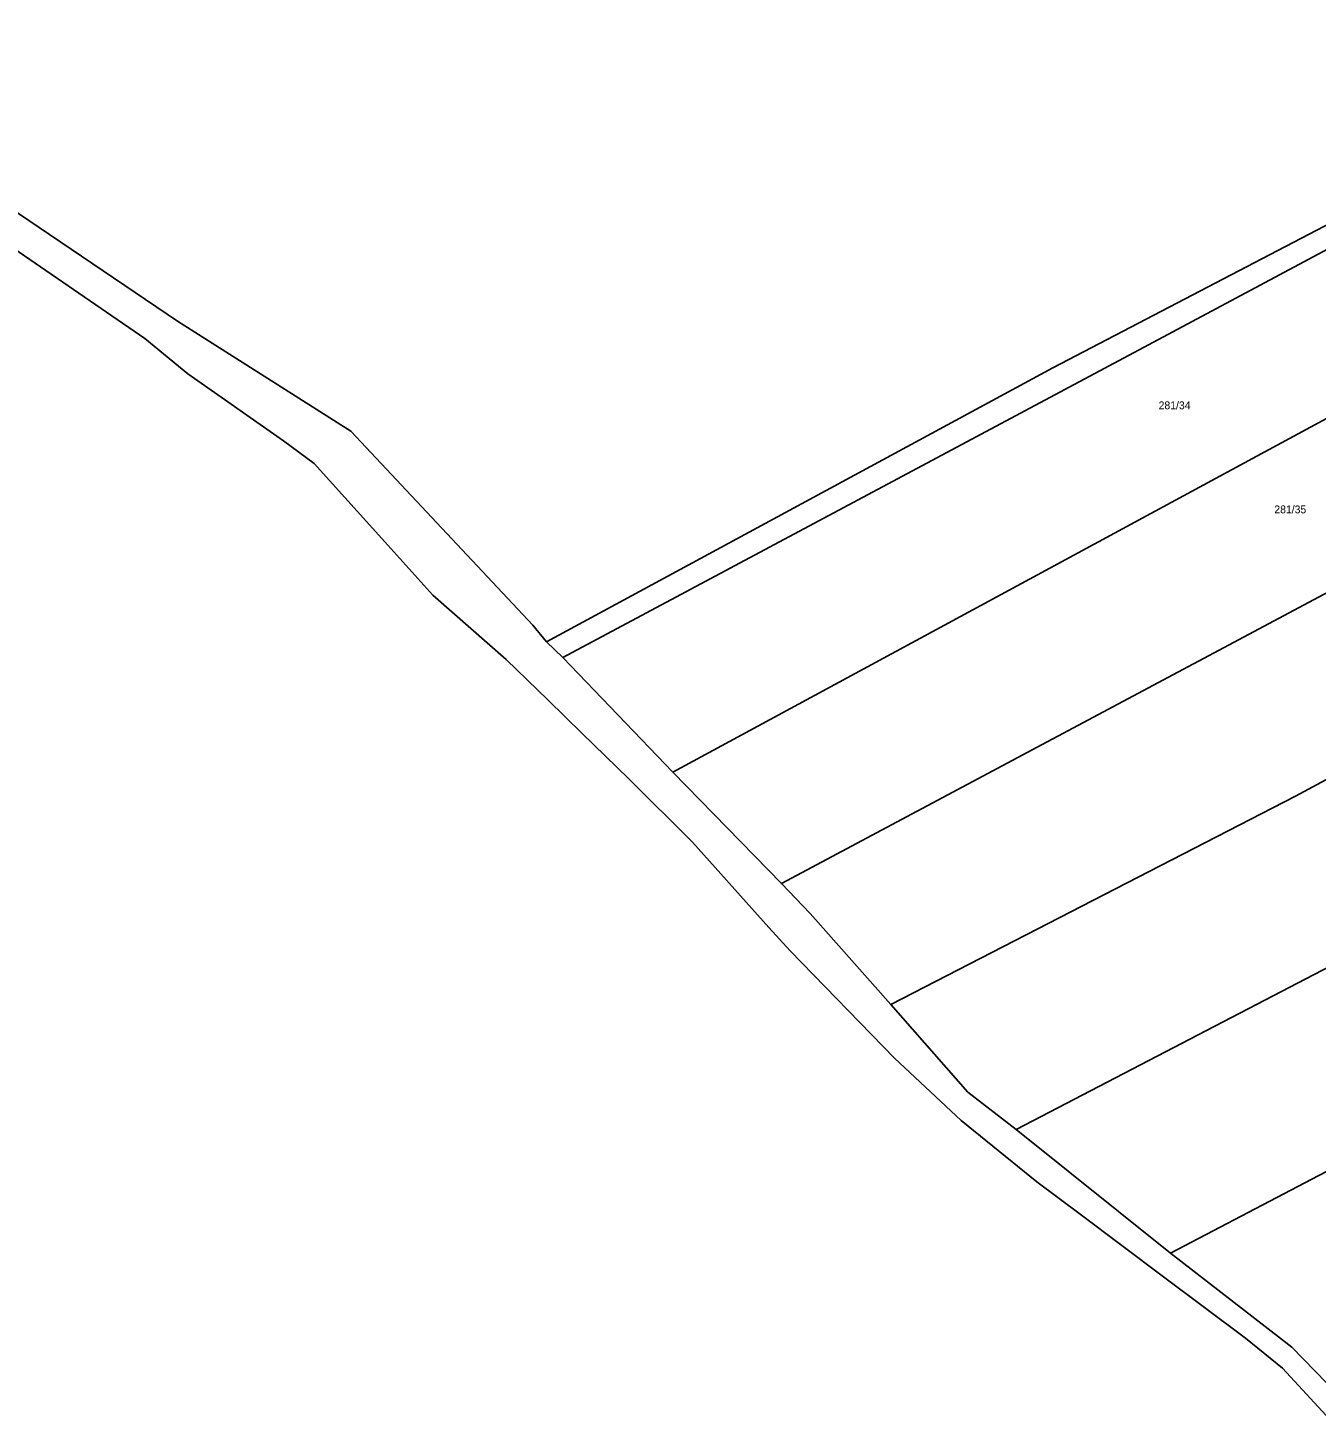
# Model space of a CAD drawing. Extents: x -779723 to -777378, y -1011169 to -1009297.
# Drawn here: x -778656.8 to -778375.8, y -1011055 to -1010750.5 of the extents above; entities that cross this region are included whole.
import ezdxf

# ---------------------------------------------------------------- set-up
doc = ezdxf.new("R2010")
doc.units = 0
doc.layers.add('KN_HRANICE', color=7, linetype='Continuous')
doc.layers.add('KN_PARCELY', color=7, linetype='Continuous')

msp = doc.modelspace()

# ---------------------------------------------------------------- linework, layer by layer
at = {"layer": 'KN_HRANICE'}
for p, q in [((-778412.34, -1010819.61), (-778282.98, -1010750.53)), ((-778676.79, -1010778.85), (-778624.16, -1010814.46)), ((-778267.44, -1010778.23), (-778392.34, -1010845.85)), ((-778631.26, -1010818.25), (-778679.13, -1010785.37)), ((-778433.26, -1010824.65), (-778357.59, -1010785.18)), ((-778624.16, -1010814.46), (-778586.31, -1010838.48)), ((-778621.86, -1010825.98), (-778631.26, -1010818.25)), ((-778540.08, -1010887.83), (-778412.34, -1010819.61)), ((-778601.01, -1010840.56), (-778621.86, -1010825.98)), ((-778543.66, -1010884.4), (-778433.26, -1010824.65)), ((-778586.31, -1010838.48), (-778546.61, -1010880.74)), ((-778594.3, -1010845.53), (-778601.01, -1010840.56)), ((-778235.35, -1010839.63), (-778380.28, -1010918.01)), ((-778578.28, -1010863.29), (-778594.3, -1010845.53)), ((-778392.34, -1010845.85), (-778516.11, -1010912.84)), ((-778568.44, -1010874.2), (-778578.28, -1010863.29)), ((-778556.56, -1010884.61), (-778568.44, -1010874.2)), ((-778492.42, -1010937.08), (-778372.93, -1010873.38)), ((-778546.61, -1010880.74), (-778543.66, -1010884.4)), ((-778543.66, -1010884.4), (-778540.08, -1010887.83)), ((-778552.44, -1010888.22), (-778556.56, -1010884.61)), ((-778543.31, -1010897.11), (-778552.44, -1010888.22)), ((-778540.08, -1010887.83), (-778516.11, -1010912.84)), ((-778535.87, -1010904.34), (-778543.31, -1010897.11)), ((-778525.77, -1010914.17), (-778535.87, -1010904.34)), ((-778511.84, -1010928.07), (-778525.77, -1010914.17)), ((-778516.11, -1010912.84), (-778492.42, -1010937.08)), ((-778380.28, -1010918.01), (-778468.57, -1010963.46)), ((-778495.13, -1010946.65), (-778511.84, -1010928.07)), ((-778492.42, -1010937.08), (-778486.13, -1010943.65)), ((-778253.66, -1010937.12), (-778407.53, -1011017.65)), ((-778486.13, -1010943.65), (-778468.57, -1010963.46)), ((-778490.52, -1010951.78), (-778495.13, -1010946.65)), ((-778441.21, -1010990.73), (-778362.13, -1010949.54)), ((-778467.75, -1010975.19), (-778490.52, -1010951.78)), ((-778468.57, -1010963.46), (-778451.73, -1010982.61)), ((-778453.23, -1010988.79), (-778467.75, -1010975.19)), ((-778451.73, -1010982.61), (-778441.21, -1010990.73)), ((-778436.69, -1011002.15), (-778453.23, -1010988.79)), ((-778441.21, -1010990.73), (-778407.53, -1011017.65)), ((-778427.3, -1011009.18), (-778436.69, -1011002.15)), ((-778409.1, -1011022.81), (-778427.3, -1011009.18)), ((-778407.53, -1011017.65), (-778381.12, -1011038.16)), ((-778391.18, -1011036.23), (-778409.1, -1011022.81)), ((-778383.16, -1011042.74), (-778391.18, -1011036.23)), ((-778381.12, -1011038.16), (-778373.57, -1011045.99)), ((-778371.88, -1011054.95), (-778383.16, -1011042.74))]:
    msp.add_line(p, q, dxfattribs=at)

# ---------------------------------------------------------------- texts
at = {"layer": 'KN_PARCELY'}
for s, p in [('281/34', (-778410.15, -1010833.67)), ('281/35', (-778384.91, -1010856.36))]:
    msp.add_text(s, height=1.7, dxfattribs=at).set_placement(p)

doc.saveas('drawing.dxf')
